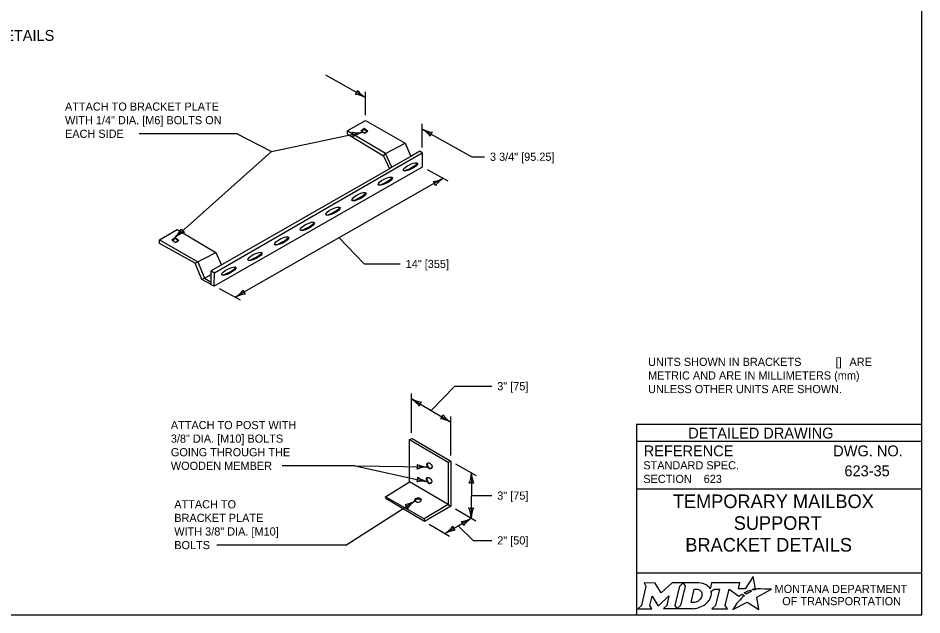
# Model space of a CAD drawing. Extents: x 49991.4 to 50021, y 49987.6 to 50011.4.
# Drawn here: x 50014.29 to 50020.94, y 49999.89 to 50004.28 of the extents above; entities that cross this region are included whole.
import ezdxf

# ---------------------------------------------------------------- set-up
doc = ezdxf.new("R2010")
doc.units = 0
for name, color, linetype in [('Default', 7, 'Continuous'), ('Level 1', 7, 'Continuous'), ('Level 2', 7, 'Continuous'), ('Level 3', 7, 'Continuous'), ('Level 4', 7, 'Continuous')]:
    doc.layers.add(name, color=color, linetype=linetype)

# ---------------------------------------------------------------- blocks, each defined once
blk = doc.blocks.new('ARR')
at = {"layer": 'Level 3'}
for centre, radius, start, end in [((1.5, 37), 37.1, 247.456, 267.6395), ((-21.4, 0), 9.13, 342.1388, 17.8612), ((1.9, -38.8), 38.8, 92.8273, 112.0772)]:
    blk.add_arc(centre, radius, start, end, dxfattribs=at)

msp = doc.modelspace()

# ---------------------------------------------------------------- linework, layer by layer
at = {"layer": 'Default'}
for points in [[(50019.7003, 50000.0679), (50019.69, 50000.0735), (50019.7016, 50000.0763), (50019.7132, 50000.0783), (50019.6958, 50000.1684), (50019.6363, 50000.0771), (50019.589, 50000.0764), (50019.5993, 50000.1205), (50019.3901, 50000.1206), (50019.38, 50000.0781), (50019.3742, 50000.0864)], [(50018.8933, 50000.1206), (50018.9074, 50000.0972), (50018.8739, 49999.9539), (50018.8482, 49999.9314), (50018.9498, 49999.9314), (50018.9363, 49999.9542), (50018.9525, 50000.0243), (50018.9962, 49999.9553), (50019.0015, 49999.9553), (50019.0766, 50000.0248), (50019.0602, 49999.9537), (50019.0355, 49999.9317), (50019.1371, 49999.9317), (50019.1233, 49999.955), (50019.1565, 50000.0974)], [(50019.1565, 50000.0974), (50019.1818, 50000.1206), (50019.0994, 50000.1206), (50019.0198, 50000.0476), (50018.9753, 50000.1203), (50018.8933, 50000.1206)], [(50019.2954, 50000.1206), (50019.1818, 50000.1206), (50019.1965, 50000.0977), (50019.1626, 49999.9539), (50019.1371, 49999.9317), (50019.2477, 49999.9317)], [(50019.3194, 50000.0339), (50019.3182, 50000.0258), (50019.315, 50000.0165), (50019.3108, 50000.0083), (50019.3052, 50000.0008), (50019.2987, 49999.9939), (50019.2908, 49999.9876), (50019.2825, 49999.9829), (50019.2734, 49999.979), (50019.2643, 49999.9767), (50019.2551, 49999.9758), (50019.2392, 49999.9758), (50019.2628, 50000.0758), (50019.2788, 50000.0758), (50019.2864, 50000.0752), (50019.294, 50000.0733), (50019.3006, 50000.0703), (50019.3067, 50000.0661), (50019.3115, 50000.0611), (50019.3152, 50000.0551), (50019.3179, 50000.0489), (50019.3195, 50000.0415), (50019.3195, 50000.0385), (50019.3194, 50000.0339)], [(50019.3868, 50000.0615), (50019.4114, 50000.0746), (50019.4483, 50000.0746), (50019.4197, 49999.9541), (50019.3922, 49999.9314), (50019.5084, 49999.9314), (50019.4914, 49999.9543), (50019.5196, 50000.0745), (50019.5909, 50000.0228), (50019.612, 50000.0379), (50019.6317, 50000.027)], [(50019.5759, 49999.9711), (50019.5606, 49999.9467), (50019.5559, 49999.9392), (50019.5501, 49999.9306), (50019.5478, 49999.9263), (50019.6531, 49999.9794), (50019.737, 49999.9243), (50019.7239, 50000.017), (50019.8308, 50000.0754), (50019.7815, 50000.0762), (50019.7514, 50000.0766), (50019.7306, 50000.0769), (50019.7238, 50000.0754), (50019.7189, 50000.0742), (50019.7105, 50000.0719), (50019.7003, 50000.0679)], [(50019.6499, 50000.0403), (50019.6475, 50000.0386), (50019.6292, 50000.0482), (50019.6395, 50000.0539), (50019.6436, 50000.0561), (50019.6522, 50000.0601), (50019.6579, 50000.0627), (50019.6658, 50000.0657), (50019.6731, 50000.0684), (50019.6849, 50000.061), (50019.6809, 50000.0589), (50019.6763, 50000.0564), (50019.6721, 50000.0542), (50019.6671, 50000.0513), (50019.6652, 50000.0502), (50019.6625, 50000.0486), (50019.66, 50000.0472), (50019.6577, 50000.0456), (50019.6551, 50000.0438), (50019.6524, 50000.042), (50019.6499, 50000.0403)], [(50019.2934, 49999.939), (50019.3018, 49999.9416), (50019.3148, 49999.947), (50019.3352, 49999.958)], [(50019.5898, 49999.9872), (50019.5898, 49999.9872)]]:
    msp.add_lwpolyline(points, dxfattribs=at)
for centre, radius, start, end in [((50019.2745, 50000.0595), 0.1183, 300.91025, 339.13831), ((50019.3185, 50000.0422), 0.0709, 339.53292, 15.85821)]:
    msp.add_arc(centre, radius, start, end, dxfattribs=at)
for centre, major_axis, ratio, start_param, end_param in [((50019.2933, 50000.0732), (0.0834, -0.0037), 0.568097, 0.61298, 1.570796), ((50019.3489, 50000.0805), (0.0361, -0.0295), 0.469099, 1.225588, 1.570796), ((50019.6206, 50000.0173), (-0.0112, -0.0097), 0.021651, 3.157348, 6.283185), ((50019.5829, 49999.9791), (-0.00694, -0.00806), 0.008222, 0, 3.137361), ((50019.5996, 49999.9974), (-0.0098, -0.0102), 0.016458, 3.141593, 6.279097), ((50019.248, 50000.08), (0, 0.1484), 0.987302, 3.139398, 3.456847)]:
    msp.add_ellipse(centre, major_axis=major_axis, ratio=ratio, start_param=start_param, end_param=end_param, dxfattribs=at)
at = {"layer": 'Level 1'}
for p, q in [((50016.71, 50003.4476), (50016.8443, 50003.5217)), ((50016.8443, 50003.5217), (50017.136, 50003.355)), ((50016.9925, 50003.2809), (50016.71, 50003.4476)), ((50016.71, 50003.4476), (50016.71, 50003.4238)), ((50016.71, 50003.4238), (50016.9763, 50003.2629)), ((50016.8353, 50003.4596), (50016.8348, 50003.4657)), ((50016.9925, 50003.2809), (50017.136, 50003.355)), ((50017.136, 50003.355), (50017.1777, 50003.2577)), ((50015.7333, 50002.4021), (50017.2617, 50003.2843)), ((50016.9763, 50003.2629), (50016.9925, 50003.2809)), ((50017.0388, 50003.179), (50016.9925, 50003.2809)), ((50017.2443, 50003.2968), (50017.1777, 50003.2577)), ((50017.2617, 50003.2843), (50017.2443, 50003.2968)), ((50017.2617, 50003.2843), (50017.2617, 50003.1801)), ((50016.9763, 50003.2629), (50017.0208, 50003.1662)), ((50017.1777, 50003.2577), (50017.0388, 50003.179)), ((50017.0208, 50003.1662), (50015.7102, 50002.416)), ((50017.2617, 50003.1801), (50015.7322, 50002.3048)), ((50017.0388, 50003.179), (50017.0208, 50003.1662)), ((50015.3286, 50002.6437), (50015.4595, 50002.7202)), ((50015.4595, 50002.7202), (50015.7441, 50002.5516)), ((50015.3286, 50002.6187), (50015.3286, 50002.6437)), ((50015.3286, 50002.6437), (50015.6113, 50002.482)), ((50015.5925, 50002.4722), (50015.3286, 50002.6187)), ((50015.4439, 50002.6624), (50015.4437, 50002.6572)), ((50015.5925, 50002.4722), (50015.7441, 50002.5516)), ((50015.7441, 50002.5516), (50015.7848, 50002.4587)), ((50015.6113, 50002.482), (50015.6597, 50002.3621)), ((50015.6412, 50002.354), (50015.5925, 50002.4722)), ((50015.7102, 50002.416), (50015.7333, 50002.4021)), ((50015.7102, 50002.3141), (50015.7102, 50002.416)), ((50015.6597, 50002.3621), (50015.6412, 50002.354)), ((50015.7102, 50002.3172), (50015.6412, 50002.354)), ((50015.6597, 50002.3621), (50015.7102, 50002.3901)), ((50015.6597, 50002.3621), (50015.7102, 50002.3346)), ((50015.7322, 50002.3048), (50015.7333, 50002.4021)), ((50015.7322, 50002.3048), (50015.7102, 50002.3141)), ((50017.1676, 50001.176), (50017.1867, 50001.1841)), ((50017.1676, 50001.176), (50017.4524, 50001.0093)), ((50017.1676, 50000.8634), (50017.1676, 50001.176)), ((50017.4524, 50001.0093), (50017.4715, 50001.0173)), ((50017.4715, 50001.0173), (50017.4715, 50000.6851)), ((50017.4524, 50001.0093), (50017.4524, 50000.699)), ((50016.9927, 50000.7534), (50017.1676, 50000.8634)), ((50017.4524, 50000.699), (50017.1676, 50000.8634)), ((50016.9956, 50000.7384), (50016.9927, 50000.7534)), ((50017.2752, 50000.5913), (50016.9927, 50000.7534)), ((50017.2781, 50000.5728), (50016.9956, 50000.7384)), ((50017.4524, 50000.699), (50017.2752, 50000.5913)), ((50017.4715, 50000.6851), (50017.2781, 50000.5728)), ((50017.4524, 50000.699), (50017.4715, 50000.6851)), ((50017.2752, 50000.5913), (50017.2781, 50000.5728))]:
    msp.add_line(p, q, dxfattribs=at)
msp.add_lwpolyline([(50020.9378, 50008.1646), (50009.7374, 50008.1646), (50009.7374, 49999.8856), (50020.9378, 49999.8856)], close=True, dxfattribs=at)
for points in [[(50016.8095, 50003.4471), (50016.8348, 50003.4657), (50016.8621, 50003.4439), (50016.8387, 50003.4258), (50016.8095, 50003.4471)], [(50016.8133, 50003.4443), (50016.8353, 50003.4596), (50016.8581, 50003.4408)], [(50017.124, 50003.1545), (50017.1296, 50003.1551), (50017.1395, 50003.1566), (50017.1487, 50003.1595), (50017.1621, 50003.1658), (50017.1791, 50003.1748), (50017.1951, 50003.1841), (50017.2145, 50003.1977), (50017.222, 50003.2049), (50017.2251, 50003.2106)], [(50016.9389, 50003.0484), (50016.9446, 50003.049), (50016.9544, 50003.0504), (50016.9637, 50003.0533), (50016.977, 50003.0597), (50016.9941, 50003.0687), (50017.01, 50003.0779), (50017.0294, 50003.0915), (50017.0369, 50003.0988), (50017.04, 50003.1044)], [(50016.745, 50002.9348), (50016.7507, 50002.9354), (50016.7605, 50002.9368), (50016.7698, 50002.9397), (50016.7831, 50002.9461), (50016.8002, 50002.9551), (50016.8161, 50002.9643), (50016.8355, 50002.9779), (50016.843, 50002.9852), (50016.8461, 50002.9908)], [(50016.5545, 50002.8279), (50016.5602, 50002.8286), (50016.57, 50002.83), (50016.5793, 50002.8329), (50016.5926, 50002.8393), (50016.6097, 50002.8482), (50016.6256, 50002.8575), (50016.645, 50002.8711), (50016.6525, 50002.8783), (50016.6556, 50002.884)], [(50016.3654, 50002.7164), (50016.3711, 50002.717), (50016.3809, 50002.7184), (50016.3902, 50002.7213), (50016.4035, 50002.7277), (50016.4206, 50002.7367), (50016.4365, 50002.7459), (50016.4559, 50002.7595), (50016.4634, 50002.7668), (50016.4665, 50002.7724)], [(50015.4186, 50002.6437), (50015.4439, 50002.6624), (50015.4712, 50002.6405), (50015.4478, 50002.6224), (50015.4186, 50002.6437)], [(50015.4221, 50002.6411), (50015.4437, 50002.6572), (50015.4675, 50002.6376)], [(50016.1763, 50002.6089), (50016.1819, 50002.6095), (50016.1918, 50002.6109), (50016.201, 50002.6138), (50016.2143, 50002.6202), (50016.2314, 50002.6292), (50016.2473, 50002.6384), (50016.2667, 50002.652), (50016.2743, 50002.6593), (50016.2774, 50002.6649)], [(50015.9803, 50002.4952), (50015.986, 50002.4959), (50015.9958, 50002.4973), (50016.0051, 50002.5002), (50016.0184, 50002.5066), (50016.0355, 50002.5156), (50016.0514, 50002.5248), (50016.0708, 50002.5384), (50016.0783, 50002.5457), (50016.0814, 50002.5513)], [(50015.7885, 50002.3871), (50015.7941, 50002.3877), (50015.804, 50002.3891), (50015.8132, 50002.392), (50015.8265, 50002.3984), (50015.8436, 50002.4074), (50015.8595, 50002.4166), (50015.8789, 50002.4302), (50015.8865, 50002.4375), (50015.8896, 50002.4431)], [(50017.1676, 50001.176), (50017.1867, 50001.1841), (50017.4715, 50001.0173)], [(50017.2089, 50000.7241), (50017.2113, 50000.729), (50017.2133, 50000.7322), (50017.2179, 50000.7359), (50017.224, 50000.7377), (50017.2313, 50000.7388), (50017.2368, 50000.7388), (50017.2425, 50000.7371), (50017.2506, 50000.7327), (50017.2529, 50000.7299)]]:
    msp.add_lwpolyline(points, dxfattribs=at)
for centre, major_axis, ratio in [((50017.175, 50003.1821), (0.052, 0.0263), 0.298197), ((50016.99, 50003.076), (0.052, 0.0263), 0.298197), ((50016.7961, 50002.9624), (0.052, 0.0263), 0.298197), ((50016.6056, 50002.8555), (0.052, 0.0263), 0.298197), ((50016.4164, 50002.744), (0.052, 0.0263), 0.298197), ((50016.2273, 50002.6365), (0.052, 0.0263), 0.298197), ((50016.0314, 50002.5229), (0.052, 0.0263), 0.298197), ((50015.8395, 50002.4147), (0.052, 0.0263), 0.298197), ((50017.3149, 50000.9831), (-0.0145, 0.02), 0.63808), ((50017.3126, 50000.8754), (-0.0145, 0.02), 0.63808), ((50017.2304, 50000.7307), (0.0225, 0.003), 0.771515)]:
    msp.add_ellipse(centre, major_axis=major_axis, ratio=ratio, dxfattribs=at)
for points in [[(50017.2974, 50000.9997), (50017.307, 50000.956), (50017.3312, 50000.9693), (50017.3339, 50000.9709)], [(50017.2947, 50000.8913), (50017.3049, 50000.8449), (50017.3315, 50000.8627), (50017.3315, 50000.8627)]]:
    msp.add_open_spline(points, degree=2, dxfattribs=at)
at = {"layer": 'Level 3'}
for p, q in [((50016.8443, 50003.6924), (50016.5531, 50003.8551)), ((50016.8443, 50003.5617), (50016.8443, 50003.7325)), ((50017.2617, 50003.3243), (50017.2617, 50003.4993)), ((50015.9003, 50003.425), (50015.1786, 50003.425)), ((50015.9003, 50003.425), (50016.1525, 50003.2937)), ((50017.2617, 50003.4593), (50017.6256, 50003.2561)), ((50017.6256, 50003.2561), (50017.7201, 50003.2561)), ((50017.2969, 50003.1612), (50017.4512, 50003.0787)), ((50017.4159, 50003.0975), (50015.8865, 50002.2222)), ((50016.6507, 50002.6596), (50016.8344, 50002.4675)), ((50016.8344, 50002.4675), (50017.1002, 50002.4675)), ((50015.7675, 50002.2859), (50015.9217, 50002.2033)), ((50017.3266, 50001.3897), (50017.5021, 50001.568)), ((50017.5021, 50001.568), (50017.7736, 50001.568)), ((50017.1818, 50001.2241), (50017.1818, 50001.5151)), ((50017.1818, 50001.4751), (50017.4715, 50001.3043)), ((50017.4715, 50001.0573), (50017.4715, 50001.3442)), ((50016.7692, 50000.9824), (50016.231, 50000.9824)), ((50017.5062, 50000.9974), (50017.6578, 50000.9101)), ((50017.6232, 50000.93), (50017.6222, 50000.5967)), ((50017.6227, 50000.7634), (50017.7736, 50000.7634)), ((50016.6993, 50000.3994), (50017.2087, 50000.7246)), ((50017.506, 50000.6649), (50017.6568, 50000.5765)), ((50017.3127, 50000.5526), (50017.4635, 50000.4642)), ((50017.4289, 50000.4845), (50017.6222, 50000.5967)), ((50017.5256, 50000.5406), (50017.6362, 50000.4337)), ((50017.6362, 50000.4337), (50017.7736, 50000.4337)), ((50016.6993, 50000.3994), (50015.7505, 50000.3994))]:
    msp.add_line(p, q, dxfattribs=at)
for points in [[(50016.1525, 50003.2937), (50016.8242, 50003.4364)], [(50015.4439, 50002.6624), (50016.1525, 50003.2937)], [(50016.7692, 50000.9824), (50017.3018, 50000.9744)], [(50016.7692, 50000.9824), (50017.3003, 50000.8655)]]:
    msp.add_lwpolyline(points, dxfattribs=at)
at = {"layer": 'Level 4'}
for p, q in [((50020.9378, 50001.2856), (50018.8378, 50001.2856)), ((50018.8378, 50001.2856), (50018.8378, 49999.8856)), ((50020.9378, 50001.1606), (50018.8378, 50001.1606)), ((50020.5739, 50000.9455), (50020.5739, 50000.9455)), ((50019.3321, 50000.8861), (50019.3321, 50000.8861)), ((50020.9378, 50000.8106), (50018.8378, 50000.8106)), ((50019.8878, 50000.5615), (50019.8878, 50000.5615)), ((50020.9378, 50000.1925), (50018.8378, 50000.1925))]:
    msp.add_line(p, q, dxfattribs=at)

# ---------------------------------------------------------------- block references
at = {"layer": 'Level 3'}
for p, xscale, yscale, rotation in [((50016.8443, 50003.6924), 0.005999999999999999, 0.006000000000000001, -29.183145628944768), ((50017.2617, 50003.4593), 0.006, 0.006, 150.8168543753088), ((50016.8242, 50003.4364), 0.006000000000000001, 0.006, 11.989022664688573), ((50017.4159, 50003.0975), 0.005999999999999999, 0.006, 29.782234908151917), ((50015.4439, 50002.6624), 0.006, 0.005999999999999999, -138.29873176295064), ((50015.8865, 50002.2222), 0.005999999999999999, 0.006, -150.2177650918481), ((50017.1818, 50001.4751), 0.006, 0.005999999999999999, 149.47545525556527), ((50017.4715, 50001.3043), 0.006, 0.005999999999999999, -30.524544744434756), ((50017.3018, 50000.9744), 0.006, 0.006, -0.8550636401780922), ((50017.3003, 50000.8655), 0.006, 0.005999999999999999, -12.405817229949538), ((50017.6232, 50000.93), 0.006000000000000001, 0.006, 89.8432407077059), ((50017.2087, 50000.7246), 0.006, 0.006, 32.557281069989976), ((50017.6222, 50000.5967), 0.006000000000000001, 0.006, -90.15675929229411), ((50017.6222, 50000.5967), 0.006, 0.006000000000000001, 30.139792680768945), ((50017.4289, 50000.4845), 0.006, 0.006000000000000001, -149.86020731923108)]:
    msp.add_blockref('ARR', p, dxfattribs=dict(at, xscale=xscale, yscale=yscale, rotation=rotation))

# ---------------------------------------------------------------- texts
at = {"layer": 'Default'}
for s, p in [('MONTANA DEPARTMENT', (50019.854, 50000.0468)), ('OF TRANSPORTATION', (50019.9102, 49999.9568))]:
    msp.add_text(s, height=0.06, dxfattribs=at).set_placement(p)
at = {"layer": 'Level 2'}
for s, height, p in [('ATTACHMENT DETAILS', 0.08, (50013.3485, 50004.1085)), ('ATTACH TO BRACKET PLATE', 0.06, (50014.6337, 50003.595)), ('WITH 1/4" DIA. [M6] BOLTS ON', 0.06, (50014.6337, 50003.495)), ('EACH SIDE', 0.06, (50014.6337, 50003.395)), ('3 3/4" [95.25]', 0.06, (50017.7601, 50003.2261)), ('14" [355]', 0.06, (50017.1402, 50002.4375)), ('UNITS SHOWN IN BRACKETS ', 0.06, (50018.9233, 50001.7171)), ('[]', 0.06, (50020.3033, 50001.7171)), (' ARE ', 0.06, (50020.3827, 50001.7171)), ('METRIC AND ARE IN MILLIMETERS (mm) ', 0.06, (50018.9233, 50001.6171)), ('3" [75]', 0.06, (50017.8136, 50001.538)), ('UNLESS OTHER UNITS ARE SHOWN.', 0.06, (50018.9233, 50001.5171)), ('ATTACH TO POST WITH', 0.06, (50015.4124, 50001.2524)), ('3/8" DIA. [M10] BOLTS', 0.06, (50015.4124, 50001.1524)), ('GOING THROUGH THE ', 0.06, (50015.4124, 50001.0524)), ('WOODEN MEMBER', 0.06, (50015.4124, 50000.9524)), ('623-35', 0.08, (50020.3676, 50000.9055)), ('623', 0.06, (50019.3321, 50000.8561)), ('3" [75]', 0.06, (50017.8136, 50000.7334)), ('TEMPORARY MAILBOX', 0.1, (50019.1052, 50000.6715)), ('ATTACH TO', 0.06, (50015.4375, 50000.6694)), ('BRACKET PLATE', 0.06, (50015.4375, 50000.5694)), ('SUPPORT', 0.1, (50019.5533, 50000.5115)), ('WITH 3/8" DIA. [M10]', 0.06, (50015.4375, 50000.4694)), ('BOLTS', 0.06, (50015.4375, 50000.3694)), ('2" [50]', 0.06, (50017.8136, 50000.4037)), ('BRACKET DETAILS', 0.1, (50019.1973, 50000.3515))]:
    msp.add_text(s, height=height, dxfattribs=at).set_placement(p)
at = {"layer": 'Level 4'}
for s, height, p in [('DETAILED DRAWING', 0.0799, (50019.2188, 50001.1831)), ('REFERENCE', 0.08, (50018.8914, 50001.0522)), ('DWG. NO.', 0.08, (50020.2856, 50001.0522)), ('STANDARD SPEC.', 0.06, (50018.8881, 50000.9562)), ('SECTION', 0.06, (50018.8881, 50000.8562))]:
    msp.add_text(s, height=height, dxfattribs=at).set_placement(p)

doc.saveas('drawing.dxf')
